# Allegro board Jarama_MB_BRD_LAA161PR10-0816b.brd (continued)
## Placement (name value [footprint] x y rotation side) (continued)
PQ601  -  [MDV1528URH_PDFN33-8-5]  84.55 31.15 0 top
PQ602  -  [MDV1524URH_PDFN33-8-5]  90.12 34.1 180 top
PR102  -  [R_0402]  24.2 59.85 90 top
PR103  -  [R_0402]  24.2 62.54 270 top
PR104  -  [R_0402]  24.19 64.45 270 top
PR105  -  [R_0402]  26.85 65.95 90 top
PR106  -  [R_0402]  26.85 67.72 90 top
PR108  -  [R_0402]  199.46 22.92 270 top
PR109  -  [R_0402]  65.08 12.25 90 top
PR110  -  [R_0402]  194.49 23.41 0 top
PR111  -  [R_0402]  64.19 12.25 90 top
PR112  -  [R_0402]  63.21 12.24 180 top
PR113  -  [R_0402]  61.44 12.24 180 top
PR115  -  [R0402_0OHM]  58.87 7.63 180 top
PR116  -  [R_0402]  99.62 2.73 270 bottom
PR118  -  [R_0402]  101.39 1.81 90 bottom
PR119  -  [R_0402]  103.19 1.81 90 bottom
PR120  -  [R_0402]  107.87 5.19 270 bottom
PR121  -  [R_0402]  107.87 3.31 270 bottom
PR122  -  [R_1206]  106.46 7.16 270 bottom
PR123  -  [R_0402]  197.95 20.07 0 top
PR124  -  [R_0402]  200.67 19.19 180 top
PR125  -  [R_0402]  198.86 19.19 180 top
PR126  -  [R_0402]  202.47 19.19 180 top
PR201  -  [R_1206_4P-D]  70.71 13.95 0 top
PR202  -  [R_0603]  28.95 56.37 180 top
PR203  -  [R_0402]  28.84 57.51 180 bottom
PR206  -  [R_0402]  27.79 55.23 0 top
PR208  -  [R_0402]  101.76 3.46 180 top
PR209  -  [R_1206]  105.39 9.05 180 bottom
PR210  -  [R_1206]  105.4 11.03 180 bottom
PR211  -  [R_0603]  97.72 10.08 90 bottom
PR213  -  [R_0402]  101.4 4.35 90 top
PR216  -  [R_1206_4P-D]  91.69 18.61 270 bottom
PR220  -  [R_1206]  85.46 13.7 0 bottom
PR223  -  [R_0402]  103.19 3.56 180 bottom
PR224  -  [R_0402]  96.7 2.73 270 bottom
PR225  -  [R_0402]  91.64 1.68 90 bottom
PR226  -  [R_0402]  102.28 4.45 0 bottom
PR230  -  [R_0402]  95.14 4.43 180 top
PR238  -  [R0402_0OHM]  102.33 1.81 90 bottom
PR239  -  [R0402_0OHM]  98.62 2.73 270 bottom
PR240  -  [R0402_0OHM]  97.61 2.73 270 bottom
PR311  -  [R_0402]  192.46 30.59 90 top
PR312  -  [R_1206]  191.06 45.83 0 bottom
PR313  -  [R_1206]  189.29 46.08 180 bottom
PR316  -  [R_0402]  189.77 31.5 270 top
PR318  -  [R_0402]  189.55 32.8 90 bottom
PR335  -  [R0402_0OHM]  190.7 30.59 90 top
PR344  -  [R0402_0OHM]  195.33 33.64 180 top
PR345  -  [R0402_0OHM]  187.64 33.28 180 top
PR348  -  [R_0402]  192.86 35.24 270 bottom
PR351  -  [R_0402]  188.21 34.91 0 bottom
PR352  -  [R_0402]  191.33 33.71 270 bottom
PR353  -  [R_0402]  191.57 30.59 90 top
PR354  -  [R_0402]  190.44 32.8 90 bottom
PR355  -  [R_0603]  195.83 36.05 180 top
PR356  -  [R_0603]  186.81 35.86 180 top
PR404  -  [R0402_0OHM]  91.5 50.22 270 top
PR405  -  [R0402_0OHM]  227.87 40.76 180 top
PR422  -  [R_0402]  84.45 49.13 0 top
PR425  -  [R_0402]  85.36 51.8 180 top
PR427  -  [R_0402]  84.45 50.02 0 top
PR428  -  [R0402_0OHM]  84.45 52.69 0 top
PR429  -  [R_1206]  89.73 54.4 270 bottom
PR432  -  [R_1206]  222.7 38.65 270 bottom
PR433  -  [R_0402]  224.59 35.53 90 top
PR434  -  [R0402_0OHM]  221.18 38.41 270 top
PR437  -  [R_0402]  225.49 35.53 90 top
PR438  -  [R_0402]  222.64 36.43 180 top
PR505  -  [R0402_0OHM]  198.38 56.88 180 top
PR506  -  [R_0603]  196.91 64.31 90 top
PR507  -  [R_1206]  197.39 65.83 270 bottom
PR508  -  [R0402_0OHM]  198.39 57.77 180 top
PR601  -  [R_0603]  91.43 33.26 0 bottom
PR604  -  [R_0402]  93.91 29.5 90 bottom
PR605  -  [R_1206]  90.1 34.59 90 bottom
PR606  -  [R_0603]  97.42 31.1 0 bottom
PR608  -  [R_0402]  101.68 37.07 180 bottom
PR610  -  [R_0402]  100.77 34.91 0 bottom
PR611  -  [R_0402]  101.68 31.35 180 bottom
PR613  -  [R0402_0OHM]  101.68 32.24 180 bottom
PR615  -  [R0402_0OHM]  101.68 34.02 180 bottom
PR701  -  [R_0402]  105.81 60.69 180 bottom
PR702  -  [R_0402]  97.4 44.23 90 top
PR703  -  [R_0402]  104.7 59.5 270 top
PR704  -  [R_0402]  105.81 58.91 180 bottom
PR706  -  [R_0402]  102.48 53.88 90 top
PR707  -  [R_0402]  99.23 45.19 0 top
PR708  -  [R_0402]  99.23 44.18 0 top
PR709  -  [R_0402]  103.38 59.16 180 bottom
PR710  -  [R_0402]  105.64 58.53 0 top
PR711  -  [R_0402]  103.38 58.28 180 bottom
PR712  -  [R_0402]  104.26 54.8 270 top
PR713  -  [R_0402]  103.37 54.8 270 top
PR714  -  [R_0402]  103.4 60.94 180 bottom
PR715  -  [R_0603]  92.08 51.8 0 top
PR717  -  [R_0402]  104.7 61.53 270 top
PR718  -  [R0402_0OHM]  100.73 55.01 180 bottom
PR719  -  [R_1206]  101.48 48.12 180 bottom
PR720  -  [R_0402]  100.73 54.02 180 bottom
PR721  -  [R_0402]  101.02 56.42 90 bottom
PR723  -  [R_0402]  101.15 54.8 270 top
PR725  -  [R_0603]  100.01 55.04 270 top
PR726  -  [R_0402]  97.28 60.26 270 top
PR727  -  [R_0402]  97.28 62.04 270 top
PR731  -  [R_0603]  95.76 58.15 0 top
PR735  -  [R_0402]  95.43 54.9 90 top
PR736  -  [R_0402]  96.64 55.86 0 top
PR737  -  [R_0402]  96.37 54.85 0 top
PR744  -  [R_0402]  95.4 61.54 180 top
PR745  -  [R_0402]  105.15 53.88 90 top
PU201  -  [BQ24715RGRR_QFN20_3P5X3P5]  100.46 7.21 270 bottom
PU301  -  [TPS51285BRUKR_QFN20_3X3]  189.76 33.29 0 top
PU405  -  [TLV62150RGTR_QFN16_3X3]  89.08 51.51 180 top
PU406  -  [TLV62150RGTR_QFN16_3X3]  222.61 40.1 270 top
PU501  -  [TPS51362RVER_QFN28_4P5X3P5]  198.02 62.85 180 top
PU601  -  [G5616ARZ1U_TQFN20_3X3]  96.03 35.82 0 bottom
PU701  -  [TPS51622RSM_QFN32_4X4]  99.63 56.87 0 top
PU702  -  [CSD97374CQ4M_SON8_3P5X4P5]  98.44 53.14 270 bottom
Q4  -  [SSM3K7002FU_SC70-3]  197.69 49.33 180 bottom
Q5  -  [SSM3K7002FU_SC70-3]  177.82 68.31 90 top
Q6  -  [SSM3K7002FU_SC70-3]  16.07 18.55 180 bottom
Q34  -  [SSM3K7002FU_SC70-3]  257.74 53.01 0 top
Q39  -  [SSM3K7002FU_SC70-3]  177.03 61.69 0 bottom
Q70  -  [SI3457BDV-T1-E3_TSOP6]  91.39 65.68 90 top
Q71  -  [SSM3K7002FU_SC70-3]  93.68 67.52 180 top
Q107  -  [SSM3K7002FU_SC70-3]  23.95 21 180 bottom
Q134  -  [SSM3K7002FU_SC70-3]  38.97 21.37 90 top
Q135  -  [SSM3K7002FU_SC70-3]  191.24 62.66 0 top
Q136  -  [SSM3K7002FU_SC70-3]  191.17 67.52 270 top
Q305  -  [SSM3K7002FU_SC70-3]  90.42 60.84 270 top
Q311  -  [SSM3K7002FU_SC70-3]  155.58 11.59 270 bottom
Q326  -  [SSM3K7002FU_SC70-3]  141.66 9.38 180 bottom
Q329  -  [AO3419L_SOT23-3]  141.67 5.19 180 bottom
Q330  -  [AO3419L_SOT23-3]  189.03 68.97 0 bottom
Q344  -  [SSM3K7002FU_SC70-3]  226.4 46.71 0 top
Q346  -  [SSM3K7002FU_SC70-3]  228.79 46.69 0 top
Q347  -  [MMBT3904_SOT23-3]  223.09 46.65 0 top
Q348  -  [SSM3K7002FU_SC70-3]  174.17 52.49 180 top
Q350  -  [SSM3K7002FU_SC70-3]  169.34 52.54 90 bottom
Q351  -  [SSM3K7002FU_SC70-3]  163.33 31.61 90 bottom
Q352  -  [DMN66D0LDW-7_SOT363-6]  202.81 51.53 90 top
Q359  -  [DMN66D0LDW-7_SOT363-6]  251.2 47.68 270 top
Q360  -  [SIS412DN-T1-GE3_POWERPAK8-5]  181.1 60.66 270 top
Q361  -  [SI1553CDL-T1-GE3_SC70-6]  182.54 59.17 0 bottom
Q362  -  [SSM3K7002FU_SC70-3]  183.72 60.94 270 bottom
Q363  -  [SSM3K7002FU_SC70-3]  177.03 59.16 0 top
Q364  -  [SSM3K7002FU_SC70-3]  197.85 8.62 90 bottom
Q365  -  [SSM3K7002FU_SC70-3]  164.21 10.94 270 bottom
Q366  -  [DMN66D0LDW-7_SOT363-6]  271.36 42.61 180 top
Q367  -  [DMN66D0LDW-7_SOT363-6]  270.06 43.76 0 top
QA1  -  [DMN66D0LDW-7_SOT363-6]  15.42 17.32 0 bottom
QA3  -  [DMN66D0LDW-7_SOT363-6]  20.46 13.76 180 top
QA6  -  [DMN66D0LDW-7_SOT363-6]  18.46 3.86 0 top
QC5  -  [SSM3K7002FU_SC70-3]  155.89 68.62 180 top
QH3  -  [DMN66D0LDW-7_SOT363-6]  178.32 55.27 270 top
QH4  -  [DMN66D0LDW-7_SOT363-6]  213.94 68.24 180 top
R1  -  [R_0402]  270.58 38.79 90 top
R4  -  [R_0402]  269.07 44.79 90 top
R7  -  [R_0402]  33.13 20.05 0 top
R11  -  [R_0402]  279.38 38.12 90 top
R23  -  [R_0402]  23.37 3.39 270 top
R24  -  [R_0402]  29.22 3.39 270 top
R25  -  [R_0402]  18.13 15.45 0 bottom
R26  -  [R_0402]  24.26 2.47 90 top
R27  -  [R_0402]  28.33 2.47 90 top
R31  -  [R_0402]  35.59 23.07 0 top
R34  -  [R_0402]  30.41 7.45 0 top
R36  -  [R_0402]  271.6 39.71 270 top
R162  -  [R_0402]  188.88 66.91 180 top
R163  -  [R_0402]  189.46 68.13 90 top
R216  -  [R0603_0OHM]  213.8 48.94 90 top
R219  -  [R_0402]  204.53 47.68 270 top
R221  -  [R_0402]  213.1 48.19 270 bottom
R225  -  [R_0402]  206.31 46.79 90 top
R229  -  [R_0402]  204.74 49.64 180 bottom
R230  -  [R_0402]  204.74 50.53 180 bottom
R232  -  [R_0402]  215.27 46.22 180 bottom
R233  -  [R_0402]  204.2 50.27 0 top
R240  -  [R_0402]  203 59.09 90 top
R253  -  [R0402_0OHM]  212.16 59.11 270 bottom
R265  -  [R0402_0OHM]  105.02 39.16 90 bottom
R290  -  [R_0402]  172.92 67.04 0 top
R296  -  [R_0402]  257.74 50.96 90 top
R297  -  [R_0402]  195.83 49 0 bottom
R298  -  [R_0402]  179.95 68.11 90 top
R300  -  [R_0402]  177.16 63.33 180 bottom
R341  -  [R_0402]  204.78 40.83 270 top
R342  -  [R_0402]  196.35 30.08 180 top
R501  -  [R_0402]  197.61 59.67 0 bottom
R503  -  [R_0402]  197.61 58.78 0 bottom
R531  -  [R_0603]  87.23 67.99 270 top
R535  -  [R_0402]  90.15 67.27 0 bottom
R536  -  [R_0402]  91.94 67.27 0 bottom
R537  -  [R_0402]  238.96 57.39 0 top
R540  -  [R_0402]  174.76 69.02 270 top
R541  -  [R_0805]  91.6 64.31 270 top
R545  -  [R_0402]  171.82 69.58 0 bottom
R604  -  [R_0402]  213.99 47.28 90 bottom
R607  -  [R_0402]  211.27 59.11 270 bottom
R608  -  [R_0402]  106.67 37.03 270 bottom
R741  -  [R_0402]  221.11 59.34 90 top
R742  -  [R_0402]  220.1 59.34 90 top
R743  -  [R_0402]  232.42 38.73 270 top
R744  -  [R_0402]  231.4 38.73 270 top
R746  -  [R_0402]  201.73 60.77 270 top
R819  -  [R0402_0OHM]  244.05 60.9 270 top
R854  -  [R_0402]  240.04 59.29 180 top
R855  -  [R_0402]  240.04 60.18 180 top
R884  -  [R_0402]  47.53 3.81 270 top
R886  -  [R_0402]  51 2.9 270 bottom
R921  -  [R0402_0OHM]  214.23 51.42 0 top
R922  -  [R_0402]  204.23 54.59 180 bottom
R923  -  [R_0402]  186.35 69.77 270 bottom
R924  -  [R0402_0OHM]  187.53 67.8 0 top
R930  -  [R_0402]  209.86 59.11 270 top
R931  -  [R_0402]  208.03 58.15 180 top
R933  -  [R_0402]  214.55 40.39 0 bottom
R934  -  [R0402_0OHM]  211.64 58.2 90 top
R935  -  [R_0402]  207.97 58.2 90 bottom
R936  -  [R_0402]  215.46 41.28 180 bottom
R937  -  [R_0402]  180.94 26.2 0 top
R938  -  [R_0402]  182.8 26.31 90 top
R939  -  [R_0402]  202.2 56.37 180 bottom
R940  -  [R_0402]  152.27 31.22 0 bottom
R942  -  [R_0402]  223.65 50.59 180 top
R943  -  [R_0402]  140.02 9.05 90 bottom
R944  -  [R_0402]  157.8 12.17 270 bottom
R945  -  [R_0402]  158.69 11.26 90 bottom
R946  -  [R_0402]  153.18 32.11 180 bottom
R947  -  [R_0402]  133.89 46.57 270 top
R948  -  [R_0402]  134.77 45.65 90 top
R949  -  [R_0402]  83.61 67.52 0 top
R950  -  [R_0402]  156.79 11.26 90 bottom
R951  -  [R_0402]  83.61 66.61 270 top
R953  -  [R_0402]  37.57 15.4 0 bottom
R955  -  [R_0402]  40.66 8.34 270 bottom
R957  -  [R_0402]  106.44 64.24 180 bottom
R973  -  [R_0402]  186.12 12.51 270 bottom
R974  -  [R0402_0OHM]  185.24 11.59 90 bottom
R975  -  [R_0402]  209.35 39.28 90 top
R976  -  [R_0402]  199.79 50.12 270 bottom
R977  -  [R_0402]  200.65 50.35 0 bottom
R978  -  [R_0402]  200.65 52.13 0 bottom
R979  -  [R_0402]  200.65 51.24 0 bottom
R982  -  [R0402_0OHM]  208.97 58.2 90 top
R983  -  [R0402_0OHM]  215.83 67.47 90 top
R984  -  [R0402_0OHM]  211.78 63.79 90 top
R985  -  [R_0402]  215.86 66.61 180 top
R986  -  [R_0402]  212.67 63.79 90 top
R987  -  [R0402_0OHM]  208.91 52.7 270 top
R988  -  [R0402_0OHM]  189.53 65.97 0 top
R989  -  [R_0402]  143.33 9.94 90 bottom
R990  -  [R0402_0OHM]  195.22 67.31 90 top
R1003  -  [R_0402]  240.04 61.96 180 top
R1004  -  [R_0402]  215.21 59.24 90 top
R1005  -  [R_0402]  216.19 59.25 90 top
R1006  -  [R_0402]  132.64 68.04 90 top
R1007  -  [R_0402]  133.66 68.04 90 top
R1008  -  [R_0402]  134.68 68.04 90 top
R1009  -  [R_0402]  135.69 68.04 90 top
R1010  -  [R_0402]  137.41 68.05 90 top
R1011  -  [R_0402]  138.42 68.05 90 top
R1012  -  [R_0402]  131.63 68.04 90 top
R1013  -  [R_0402]  130.61 68.04 90 top
R1014  -  [R_0402]  128.58 68.04 90 top
R1015  -  [R_0402]  129.66 68.04 90 top
R1016  -  [R0402_0OHM]  137.48 71.79 0 top
R1017  -  [R0402_0OHM]  137.48 70.93 0 top
R1026  -  [R_0402]  188.28 50.58 180 top
R1033  -  [R_0402]  138.35 66.49 0 top
R1034  -  [R_0402]  136.57 66.49 0 top
R1035  -  [R_0402]  238.31 42.45 90 top
R1036  -  [R_0402]  235.64 42.45 90 top
R1090  -  [R_0402]  240.06 62.82 180 top
R1092  -  [R_0402]  243.19 59.57 180 top
R1099  -  [R_0402]  241.08 55.96 0 top
R1100  -  [R_0402]  184.35 12.51 270 bottom
R1103  -  [R_0402]  49.85 4.05 0 bottom
R1116  -  [R_0402]  252.23 67.8 180 top
R1117  -  [R_0402]  264.47 53.88 90 top
R1118  -  [R_0402]  265.36 53.88 90 top
R1119  -  [R_0402]  27.5 44.06 270 top
R1120  -  [R_0402]  28.39 44.06 270 top
R1125  -  [R0603_0OHM]  36 12.45 270 bottom
R1128  -  [R0603_0OHM]  238.25 46.34 0 top
R1129  -  [R_0603]  200.84 55.29 270 top
R1131  -  [R0402_0OHM]  218.07 54.59 180 top
R1132  -  [R_0402]  117.07 51.04 0 top
R1133  -  [R0402_0OHM]  210.75 58.2 90 top
R1135  -  [R0402_0OHM]  251.31 68.69 0 top
R1136  -  [R_0402]  251.31 69.55 0 top
R1137  -  [R_0402]  227.34 49.96 180 top
R1140  -  [R_0402]  33.96 17.75 90 bottom
R1141  -  [R_0402]  240.06 63.71 180 top
R1142  -  [R_0402]  187.01 11.59 90 bottom
R1143  -  [R_0402]  251.31 66.91 0 top
R1152  -  [R_0402]  126.52 65.08 90 top
R1153  -  [R_0402]  127.77 65.08 90 top
R1156  -  [R_0402]  203.32 56.24 0 bottom
R1157  -  [R_0402]  141.03 66.53 0 top
R1158  -  [R0402_0OHM]  252.02 63.66 90 top
R1161  -  [R_0402]  95.38 66.32 0 top
R1162  -  [R_0402]  188.28 49.69 180 top
R1164  -  [R_0402]  261.75 49.64 180 top
R1165  -  [R_0402]  267.9 46.98 270 top
R1166  -  [R0402_0OHM]  265.88 46.98 270 top
R1167  -  [R0402_0OHM]  27.63 50.26 90 top
R1168  -  [R_0402]  25.85 50.26 90 top
R1169  -  [R_0402]  180.66 60.16 90 bottom
R1170  -  [R_0402]  261.75 48.75 180 top
R1174  -  [R_0402]  232.92 46.46 180 top
R1179  -  [R_0402]  117.29 58.71 180 bottom
R1180  -  [R_0402]  111.31 56.62 0 top
R1182  -  [R_0402]  33.07 17.75 90 bottom
R1185  -  [R_0402]  181.88 56.35 270 top
R1186  -  [R_0402]  37.98 4.49 180 top
R1187  -  [R_0402]  36.12 3.42 270 top
R1188  -  [R0402_0OHM]  236.1 69.71 180 top
R1190  -  [R_0402]  184.8 64.75 180 bottom
R1197  -  [R_0402]  229.99 49.94 90 top
R1198  -  [R_0402]  119.37 49.64 0 bottom
R1200  -  [R_0402]  172.52 51.24 270 top
R1202  -  [R_0402]  216.87 46.08 180 top
R1203  -  [R_0402]  221.44 50.61 90 top
R1204  -  [R0402_0OHM]  230.13 69.71 180 top
R1205  -  [R_0402]  172.48 53.32 0 bottom
R1208  -  [R_0402]  264.66 27.16 0 bottom
R1209  -  [R0402_0OHM]  225.48 51.49 270 top
R1210  -  [R_0402]  224.59 51.49 270 top
R1211  -  [R_0402]  115.51 58.73 270 bottom
R1212  -  [R_0402]  225.48 45.68 180 top
R1213  -  [R_0402]  267.02 46.98 270 top
R1214  -  [R_0402]  26.74 50.26 90 top
R1215  -  [R_0402]  217.79 52.43 0 top
R1216  -  [R_0402]  264.72 46.07 90 top
R1217  -  [R_0402]  28.89 51.11 270 top
R1218  -  [R0402_0OHM]  126.52 66.91 270 top
R1219  -  [R0402_0OHM]  127.77 66.91 270 top
R1220  -  [R_0402]  249.21 58.16 0 top
R1221  -  [R0402_0OHM]  247.84 57.25 90 top
R1222  -  [R0402_0OHM]  246.95 57.25 90 top
R1223  -  [R_0402]  246.06 58.17 270 top
R1224  -  [R_0402]  164.79 66.07 90 top
R1225  -  [R_0402]  165.68 66.07 90 top
R1226  -  [R0603_0OHM]  236.91 50.21 90 top
R1227  -  [R0402_0OHM]  141.08 68.82 270 top
R1228  -  [R_0402]  183.46 11.59 90 bottom
R1229  -  [R_0402]  251.31 66.02 0 top
R1230  -  [R_0402]  237.18 57.39 0 top
R1231  -  [R0402_0OHM]  216.77 51.9 270 top
R1232  -  [R0402_0OHM]  216.77 49.82 270 top
R1233  -  [R_0402]  215.84 49.84 270 top
R1234  -  [R_0402]  241.89 58.71 0 top
R1235  -  [R_0402]  241.66 57.83 0 top
R1236  -  [R_0402]  241.66 56.92 0 top
R1237  -  [R_0402]  240.71 58.16 270 top
R1238  -  [R0402_0OHM]  212.99 45.93 180 top
R1239  -  [R_0402]  212.99 45.04 180 top
R1240  -  [R_1206]  176.64 63.78 90 top
R1241  -  [R_0402]  244.56 42.05 180 top
R1242  -  [R0603_0OHM]  191.52 11.54 180 bottom
R1243  -  [R_0402]  243.39 43.86 270 top
R1249  -  [R_0402]  215.23 55.46 180 bottom
R1250  -  [R_0402]  238.99 51.93 0 top
R1251  -  [R_0402]  245.17 58.17 270 top
R1252  -  [R0402_0OHM]  256.09 52.36 90 top
R1253  -  [R_0402]  256.09 55.18 270 top
R1255  -  [R_0402]  228.21 50.91 0 top
R1256  -  [R_0402]  228.21 51.8 0 top
R1257  -  [R0402_0OHM]  170.88 12.25 270 bottom
R1258  -  [R0402_0OHM]  170 12.25 270 bottom
R1260  -  [R0603_0OHM]  190.32 51.02 270 bottom
R1261  -  [R_0402]  40.24 17.63 270 bottom
R1262  -  [R_0402]  39.35 17.62 270 bottom
R1263  -  [R_0402]  40.66 9.25 0 bottom
R1264  -  [R_0402]  36.88 17.52 270 top
R1265  -  [R_0402]  41.55 11.06 270 bottom
R1266  -  [R_0402]  37.77 17.52 270 top
R1289  -  [R_0402]  182.26 36.5 270 top
R1290  -  [R_0402]  180.41 30.92 270 top
R1291  -  [R_0402]  181.37 36.5 270 top
R1292  -  [R_0402]  185.98 30.29 270 top
R1294  -  [R0402_0OHM]  181.32 30.92 270 top
R1295  -  [R_0402]  180.41 31.78 90 top
R1296  -  [R_0402]  180.4 36.2 270 top
R1297  -  [R0402_0OHM]  180.4 33.55 90 top
R1300  -  [R_0402]  195.83 8.09 0 bottom
R1301  -  [R_0402]  166.24 10.74 90 bottom
R1305  -  [R_0603]  49.02 9.13 0 top
R1306  -  [R_0603]  48.56 6.63 90 top
R1309  -  [R0402_0OHM]  117.38 51.44 180 bottom
R1310  -  [R_0402]  207.07 41.82 90 top
R1311  -  [R_0402]  116.47 52.33 0 bottom
R1312  -  [R_0402]  174.48 45.58 0 top
R1313  -  [R_0402]  221.75 54.14 180 top
R1314  -  [R0402_0OHM]  221.51 53.25 180 top
R1318  -  [R0603_0OHM]  32.19 13.89 270 bottom
R1319  -  [R0603_0OHM]  244.81 51.34 0 top
R1320  -  [R0603_0OHM]  167.76 68.88 180 top
R1321  -  [R_0603]  192.33 49.1 0 bottom
R1322  -  [R0805_0OHM]  194.17 51 90 top
R1324  -  [R_0402]  89.39 64.45 270 top
R1325  -  [R_0402]  88.5 64.45 270 top
R1326  -  [R_0603]  167.82 67.29 270 top
R1327  -  [R_0402]  217.15 55.48 0 top
R1328  -  [R_0402]  217.15 56.37 0 top
R1330  -  [R0603_0OHM]  243.69 54.06 90 top
R1331  -  [R0603_0OHM]  55.21 12.38 0 top
R1338  -  [R_0402]  216.87 46.97 180 top
R1339  -  [R_0402]  223.65 51.54 180 top
R1340  -  [R_0402]  245.5 42.03 0 top
R1341  -  [R_0402]  166.87 31.35 0 bottom
R1342  -  [R_0402]  210.75 64.63 270 top
R1343  -  [R_0402]  248.34 43.37 270 top
R1346  -  [R_0402]  249.28 47.03 0 top
R1347  -  [R_0402]  249.28 47.92 0 top
R1348  -  [R_0402]  239.91 50.9 180 top
R1349  -  [R_0402]  239.91 50.02 180 top
R1350  -  [R_0402]  252.61 48.81 180 top
R1351  -  [R_0402]  251.18 45.25 0 top
R1353  -  [R0402_0OHM]  121.72 54.54 270 top
R1355  -  [R_1206]  184.54 63.23 180 bottom
R1360  -  [R_0402]  218.93 62.59 0 top
R1361  -  [R_0402]  217.15 60.82 0 top
R1362  -  [R_0402]  217.15 59.93 0 top
R1363  -  [R_0402]  217.15 59.04 0 top
R1364  -  [R_0402]  217.15 58.15 0 top
R1365  -  [R_0402]  217.15 57.26 0 top
R1366  -  [R_0402]  203.84 27.57 0 top
R1367  -  [R_0402]  250.93 58.16 0 top
R1368  -  [R_0402]  224.77 56.37 0 top
R1369  -  [R_0402]  224.77 57.26 0 top
R1370  -  [R_0402]  224.77 54.59 0 top
R1371  -  [R_0402]  224.77 55.48 0 top
R1372  -  [R0402_0OHM]  32.3 11.82 90 top
R1373  -  [R_0402]  35.23 4.54 90 top
R1374  -  [R_0402]  36.12 4.54 90 top
R1376  -  [R_0402]  141.97 68.82 270 top
R1379  -  [R_0603]  195.76 52.37 90 top
R1380  -  [R0603_0OHM]  264.85 11.48 90 top
R1381  -  [R_0402]  184.68 57.03 180 top
R1382  -  [R_0402]  181.59 59.29 180 bottom
R1383  -  [R_0402]  181.5 58.05 180 bottom
R1384  -  [R_0402]  175.06 55.91 90 top
R1385  -  [R_0402]  175.2 58.61 270 top
R1386  -  [R_0402]  215.16 49.39 270 bottom
R1387  -  [R0402_0OHM]  196.73 9.05 180 bottom
R1388  -  [R0402_0OHM]  165.35 10.74 90 bottom
R1389  -  [R0603_0OHM]  203.89 8.68 90 top
R1390  -  [R_0402]  232.92 50.78 180 top
RA1  -  [R_0402]  45.21 12.73 180 top
RA2  -  [R0603_0OHM]  22.22 18.97 180 top
RA3  -  [R0402_0OHM]  15.17 12.38 270 bottom
RA4  -  [R0402_0OHM]  15.04 16.57 270 top
RA5  -  [R_0402]  201.81 65.9 180 top
RA6  -  [R_0402]  201.86 67.72 90 top
RA7  -  [R_0402]  166.57 66.99 270 top
RA8  -  [R_0402]  163.76 66.99 270 top
RA9  -  [R0402_0OHM]  201.81 66.78 180 top
RA10  -  [R0402_0OHM]  200.97 67.72 90 top
RA11  -  [R0402_0OHM]  44.3 15.81 0 top
RA12  -  [R0402_0OHM]  44.3 14.93 0 top
RA13  -  [R0402_0OHM]  44.3 14.04 0 top
RA14  -  [R_0402]  13.54 9.25 90 top
RA15  -  [R_0402]  15.2 13.25 180 bottom
RA16  -  [R_0402]  16.64 13.51 90 bottom
RA17  -  [R_0402]  14.37 18.33 180 top
RA18  -  [R_0402]  18.12 21.67 0 bottom
RA20  -  [R_0402]  20.37 7.49 90 top
RA21  -  [R_0402]  18.09 17.12 90 top
RA22  -  [R_0402]  17.07 17.12 90 top
RA23  -  [R_0402]  19.11 21.64 270 top
RA24  -  [R_0402]  21.22 22.84 180 top
RA25  -  [R_0402]  21.22 21.83 180 top
RA26  -  [R0402_0OHM]  19.11 10.88 270 top
RA27  -  [R_0402]  15.22 18.4 0 top
RA28  -  [R_0402]  16.64 12.45 0 bottom
RA29  -  [R_0402]  32.33 21.83 180 top
RA30  -  [R_0402]  34.74 23.05 180 top
RA31  -  [R_0402]  34.04 19.16 180 top
RA32  -  [R0603_0OHM]  31.49 29.19 0 top
RA33  -  [R_0402]  34.04 18.27 180 top
RA35  -  [R_0402]  17.8 6.71 180 top
RA36  -  [R_0402]  32.52 25.64 180 bottom
RA37  -  [R_0402]  18.22 14.77 90 top
RA38  -  [R_0402]  20 9.97 90 top
RA39  -  [R_0402]  19.11 14.77 90 top
RA41  -  [R_0402]  22.29 21.9 270 bottom
RA42  -  [R_0402]  23.62 24.11 0 bottom
RA43  -  [R_0402]  13.53 17.2 270 bottom
RA44  -  [R_0402]  19.11 18.84 90 top
RA45  -  [R_0402]  14.45 19.11 180 bottom
RA46  -  [R_0603]  30.68 6.52 270 bottom
RA47  -  [R_0603]  20.96 2.68 0 top
RA48  -  [R_0402]  14.37 20.11 180 top
RA49  -  [R_0402]  15.18 14.21 180 bottom
RA50  -  [R_0402]  14.37 19.22 180 top
RA51  -  [R_0402]  14.41 16 270 bottom
RA52  -  [R_0402]  32.26 20.94 180 top
RA53  -  [R_0402]  32.52 26.53 180 bottom
RA54  -  [R_0402]  32.33 23.6 180 top
RA55  -  [R_0402]  22.13 7.51 180 top
RA56  -  [R_0402]  30.79 13.24 90 top
RA57  -  [R0402_0OHM]  18.34 20.79 270 bottom
RA58  -  [R_0402]  47.96 13.8 90 top
RA59  -  [R_0402]  48.89 13.8 90 top
RA60  -  [R_0402]  46.06 12.73 0 top
RA61  -  [R_0402]  47.05 13.8 90 top
RA62  -  [R_0402]  46.13 13.8 90 top
RA68  -  [R_0603]  31.56 5.18 180 top
RA69  -  [R_0603]  22.36 3.89 180 top
RA75  -  [R_0402]  13.53 20.14 0 bottom
RC36  -  [R_0402]  151.24 57.51 0 top
RC41  -  [R_0402]  116.38 56.93 0 bottom
RC43  -  [R_0402]  116.38 57.82 0 bottom
RC44  -  [R_0402]  117 57.03 0 top
RC45  -  [R_0402]  120.36 58.81 180 bottom
RC46  -  [R_0402]  120.36 60.59 180 bottom
RC48  -  [R_0402]  120.36 59.7 180 bottom
RC49  -  [R0402_0OHM]  117.75 60.69 180 bottom
RC52  -  [R_0402]  122.87 56.96 270 top
RC54  -  [R_0402]  121.76 56.95 270 top
RC55  -  [R_0402]  130.1 47.1 270 top
RC58  -  [R_0402]  131.43 45.45 0 top
RC60  -  [R_0402]  131.43 46.97 0 top
RC75  -  [R_0402]  153.05 33.31 90 bottom
RC81  -  [R_0402]  120.28 50.53 180 bottom
RC92  -  [R0402_0OHM]  117.67 54.29 270 bottom
RC93  -  [R_0402]  120.21 53.65 90 bottom
RC94  -  [R_0402]  119.32 54.57 270 bottom
RC95  -  [R_0402]  120.64 55.48 0 bottom
RC96  -  [R0402_0OHM]  117.09 55.86 0 bottom
RC97  -  [R_0402]  119.45 64.14 0 bottom
RC98  -  [R0402_0OHM]  119.45 63.23 0 bottom
RC99  -  [R0402_0OHM]  120.36 62.37 180 bottom
RC100  -  [R_0402]  120.36 61.48 180 bottom
RC138  -  [R_0402]  153.36 68.89 270 top
RC146  -  [R_0402]  139.3 67.9 90 top
RC147  -  [R0402_0OHM]  160.34 66.99 270 bottom
RC148  -  [R0402_0OHM]  154.23 67.98 90 top
RC149  -  [R_0402]  116.83 59.8 0 bottom
RC150  -  [R0402_0OHM]  116.83 61.58 0 bottom
RC151  -  [R0402_0OHM]  116.96 57.89 0 top
RC152  -  [R0402_0OHM]  114.62 57.82 90 bottom
RC153  -  [R_0402]  121.68 51.42 180 bottom
RC154  -  [R_0402]  152.9 36 270 bottom
RC155  -  [R_0402]  155.01 66.91 0 bottom
RC156  -  [R_0402]  152.01 36 270 bottom
RC158  -  [R_0402]  140.19 68.82 270 top
RC159  -  [R_0402]  124.71 32.62 0 bottom
RC160  -  [R_0402]  154.18 66.53 180 top
RC161  -  [R_0402]  125.62 31.73 180 bottom
RC162  -  [R0402_0OHM]  153.79 36 270 bottom
RD1  -  [R_0402]  99.76 19.6 180 top
RD2  -  [R_0402]  109.85 21.81 90 top
RD5  -  [R_0402]  128.82 18.33 0 top
RD6  -  [R_0402]  134.61 20.44 270 top
RD7  -  [R_0402]  146.37 18.33 180 top
RD8  -  [R_0402]  157.09 20.44 270 top
RD11  -  [R_0402]  175.94 18.33 0 top
RD12  -  [R_0402]  180.9 24.42 90 top
RD13  -  [R_0402]  119.69 48.01 270 top
RD14  -  [R_0402]  120.61 45.35 180 top
RD15  -  [R_0402]  120.58 47.1 90 top
RD16  -  [R_0402]  121.47 47.1 90 top
RD17  -  [R_0402]  112.5 45.58 0 top
RD18  -  [R_0402]  117.91 47.33 270 top
RD19  -  [R_0402]  115.2 45.58 180 top
RD20  -  [R_0402]  117.02 45.5 90 top
RD21  -  [R_0402]  113.42 46.46 180 top
RD22  -  [R_0402]  117 47.51 90 top
RD23  -  [R_0402]  115.2 46.46 180 top
RD24  -  [R_0402]  118.8 46.41 90 top
RD25  -  [R_0402]  121.45 16.4 180 top
RD26  -  [R_0402]  167.05 18.45 0 top
RD27  -  [R_0402]  119.93 18.71 0 top
RD28  -  [R_0402]  169.75 18.45 180 top
RD29  -  [R_0402]  123.69 14.7 0 top
RD30  -  [R_0402]  165.42 14.9 180 top
RD31  -  [R_0402]  124.45 22.32 90 top
RD32  -  [R_0402]  170.68 20.54 90 top
RD33  -  [R_0402]  121.73 15.15 180 top
RD34  -  [R_0402]  166.19 12.73 90 top
RD35  -  [R_0402]  117.97 13.55 90 top
RD36  -  [R_0402]  168.33 14.82 90 top
RD37  -  [R_0402]  123.65 15.64 0 top
RD38  -  [R_0402]  170.88 16.17 180 top
RD39  -  [R_0402]  122.13 13.12 0 top
RD40  -  [R_0402]  163.87 12.87 180 top
RD41  -  [R_0402]  125.77 14.64 0 top
RD42  -  [R_0402]  170.31 12.66 0 top
RD43  -  [R_0402]  123.93 13.06 0 top
RD44  -  [R_0402]  172.08 13.71 270 top
RD45  -  [R_0402]  118.86 13.68 90 top
RD46  -  [R_0402]  173.85 12.79 90 top
RD47  -  [R_0402]  116.85 12.68 180 top
RD48  -  [R_0402]  172.96 12.79 90 top
RD49  -  [R_0402]  120.58 12.61 90 top
RD50  -  [R_0402]  166.26 14.9 0 top
RD51  -  [R_0402]  126.73 12.68 0 top
RD52  -  [R_0402]  168.01 12.78 90 top
RD53  -  [R_0402]  125.79 12.61 90 top
RD54  -  [R_0402]  169.47 14.38 90 top
RD55  -  [R_0402]  119.26 12.56 180 top
RD56  -  [R_0402]  167.12 12.78 90 top
RD57  -  [R_0402]  123.56 22.32 90 top
RD58  -  [R_0402]  167.63 20.56 270 top
RD59  -  [R_0402]  123.03 19.92 180 top
RD60  -  [R_0402]  170.89 17.06 180 top
RD61  -  [R_0402]  125.39 17.18 0 top
RD62  -  [R_0402]  169.74 19.34 180 top
RD63  -  [R_0402]  123.03 19.03 180 top
RD64  -  [R_0402]  169.74 20.23 180 top
RD65  -  [R_0402]  123.03 20.8 180 top
RD66  -  [R_0402]  172.51 16.3 0 top
RD67  -  [R_0402]  121.78 17.24 90 top
RD68  -  [R_0402]  168.2 16.67 90 top
RD69  -  [R_0402]  118.86 16.37 270 top
RD70  -  [R_0402]  172.53 15.43 270 top
RD71  -  [R_0402]  122.7 17.21 90 top
RD72  -  [R_0402]  171.69 20.54 90 top
RD73  -  [R_0402]  108.91 19.6 180 top
RD74  -  [R_0402]  194.49 19.87 270 top
RD75  -  [R_0402]  122.49 25.19 180 top
RD76  -  [R_0402]  169.81 24.42 180 top
RD77  -  [R_0402]  122.49 24.3 180 top
RD78  -  [R_0402]  169.81 23.53 180 top
RD79  -  [R_0402]  99.76 18.71 180 top
RD80  -  [R_0402]  108.96 21.81 90 top
RD81  -  [R_0402]  128.82 19.22 0 top
RD82  -  [R_0402]  135.5 20.44 270 top
RD83  -  [R_0402]  146.37 19.22 180 top
RD84  -  [R_0402]  157.98 20.44 270 top
RD85  -  [R_0402]  175.94 19.22 0 top
RD86  -  [R_0402]  178.44 21.06 180 top
RD87  -  [R_0402]  122.67 22.32 90 top
RD88  -  [R_0402]  125.39 16.3 0 top
RD89  -  [R_0402]  168.93 22.32 0 top
RD90  -  [R_0402]  172.51 17.18 0 top
RH2  -  [R_0402]  172.68 47.07 0 bottom
RH11  -  [R_0402]  162.25 35.28 90 bottom
RH12  -  [R_0402]  178.8 48.62 0 top
RH21  -  [R_0402]  113.09 56.62 0 top
RH23  -  [R_0402]  164.61 33.51 180 bottom
RH24  -  [R_0402]  162.07 31.61 180 bottom
RH25  -  [R_0402]  165.47 33.51 0 bottom
RH29  -  [R_0402]  214.57 44.04 90 bottom
RH31  -  [R_0402]  160.34 33.37 90 bottom
RH34  -  [R_0402]  160.34 35.28 90 bottom
RH35  -  [R_0402]  167.53 52.69 180 bottom
RH37  -  [R_0402]  167.53 50.91 180 bottom
RH38  -  [R_0402]  118.43 48.8 90 bottom
RH39  -  [R_0402]  119.37 47.86 0 bottom
RH40  -  [R_0402]  119.37 48.75 0 bottom
RH42  -  [R_0402]  156.46 36.18 0 bottom
RH43  -  [R_0402]  155.01 66.02 0 bottom
RH51  -  [R0402_0OHM]  115.07 63.08 90 bottom
RH53  -  [R_0402]  119.37 45.19 0 bottom
RH54  -  [R_0402]  186.49 55.81 270 top
RH56  -  [R_0402]  185.6 55.81 270 top
RH70  -  [R_0402]  174.95 36.51 270 bottom
RH72  -  [R_0402]  173.93 36.51 270 bottom
RH76  -  [R_0402]  147.31 67.67 0 bottom
RH77  -  [R_0402]  147.31 66.78 0 bottom
RH78  -  [R_0402]  174.26 52.43 180 bottom
RH79  -  [R_0402]  165.08 49.73 0 top
RH80  -  [R_0402]  168.89 50.53 0 top
RH81  -  [R_0402]  168.89 49.64 0 top
RH82  -  [R_0402]  166.62 51.8 0 bottom
RH83  -  [R_0402]  168.89 48.75 0 top
RH91  -  [R_0402]  167.53 54.47 180 bottom
RH95  -  [R_0402]  176.28 53.42 180 top
RH98  -  [R_0402]  177.78 56.24 0 top
RH99  -  [R_0402]  180.47 56.24 180 top
RH100  -  [R_0402]  167.51 49.16 180 bottom
RH103  -  [R_0402]  167.53 56.62 180 bottom
RH105  -  [R_0402]  178.8 52.99 180 top
RH107  -  [R_0402]  168.4 53.63 90 bottom
RH111  -  [R_0402]  177.2 53.88 90 top
RH113  -  [R_0402]  148.57 64.42 90 top
RH117  -  [R_0402]  151.26 64.5 180 top
RH123  -  [R_0402]  174.73 66.2 90 top
RH126  -  [R_0402]  167.71 36.51 270 bottom
RH128  -  [R0402_0OHM]  169.88 47.58 270 top
RH131  -  [R_0402]  165.08 54.26 0 top
RH132  -  [R0402_0OHM]  166.95 51.11 270 top
RH133  -  [R0402_0OHM]  167.84 34.35 270 bottom
RH134  -  [R_0402]  166 53.4 180 top
RH137  -  [R0402_0OHM]  176.92 49.11 0 top
RH146  -  [R_0402]  173.64 47.25 180 top
RH147  -  [R_0402]  161.3 33.37 90 bottom
RH151  -  [R_0402]  161.3 35.28 90 bottom
RH154  -  [R_0402]  175.82 45.16 180 bottom
RH158  -  [R_0402]  163.01 66.99 270 bottom
RH159  -  [R_0402]  168.73 33.43 90 bottom
RH160  -  [R_0402]  166.62 45.45 0 bottom
RH163  -  [R_0402]  156.83 45.58 0 top
RH168  -  [R_0402]  182.95 49.04 90 top
RH171  -  [R_0402]  183.01 48.12 180 top
RH180  -  [R_0402]  171.38 54.14 90 top
RH183  -  [R_0402]  186.49 49.51 270 top
RH186  -  [R_0402]  169.04 47.35 180 top
RH196  -  [R_0402]  170.11 54.14 90 top
RH248  -  [R_0402]  169.22 55.05 270 top
RH256  -  [R_0402]  166.95 52.86 270 top
RH258  -  [R_0402]  184.66 55.23 180 top
RH270  -  [R_0402]  166.86 54.08 0 top
RH271  -  [R_0402]  170.69 52.1 270 top
RH272  -  [R_0402]  166.59 47.18 0 bottom
RH274  -  [R_0402]  172.41 50.45 90 bottom
RH281  -  [R_0402]  157.66 66.99 270 bottom
RH282  -  [R_0402]  159.44 66.99 270 bottom
RH293  -  [R0402_0OHM]  174.48 47.35 0 top
RH294  -  [R_0402]  170.17 34.65 0 bottom
RH295  -  [R_0402]  175.2 51.37 270 bottom
RH296  -  [R_0402]  181.03 47.62 90 top
RH297  -  [R0402_0OHM]  176.4 46.03 0 bottom
RH298  -  [R_0402]  179.71 47.61 180 top
RH299  -  [R_0402]  177.02 47.61 0 top
RH300  -  [R_0402]  161.23 66.99 270 bottom
RH301  -  [R_0402]  172.12 56.29 90 top
RH302  -  [R_0402]  166.59 50.05 0 bottom
RH303  -  [R_0402]  172.03 36.51 270 bottom
RH309  -  [R_0402]  171.09 33.64 180 bottom
RH310  -  [R_0402]  169.04 46.46 180 top
RH313  -  [R_0402]  166.69 35.59 90 bottom
RH314  -  [R_0402]  171.58 51.19 90 top
RH315  -  [R_0402]  171.58 53.2 180 top
RH316  -  [R_0402]  171.14 35.59 90 bottom
RH337  -  [R_0402]  173.35 51.29 0 bottom
RH338  -  [R_0402]  147.5 65.34 270 top
RH340  -  [R0805_0OHM]  154.28 49.6 180 top
RH341  -  [R0603_0OHM]  155.76 45.51 90 top
RH346  -  [R0402_0OHM]  153.17 47.35 180 top
RH348  -  [R_0603]  182.05 49.54 180 top
RH350  -  [R_0603]  186.94 68.87 0 top
RH351  -  [R_0603]  170.87 49.96 270 top
RH354  -  [R_0603]  184.88 67.56 0 bottom
RH355  -  [R0603_0OHM]  161.79 65.64 180 top
RH356  -  [R0603_0OHM]  160.97 67.1 90 top
RH360  -  [R_0402]  180.4 28.22 0 top
RH363  -  [R_0402]  117.91 56.12 180 top
RH364  -  [R_0402]  177.23 12.1 180 bottom
RH365  -  [R_0402]  178.1 12.1 0 bottom
RH367  -  [R_0402]  117.91 55.1 180 top
RH369  -  [R_0402]  89.45 56.45 90 top
RH370  -  [R_0402]  85.41 56.83 90 top
RH371  -  [R_0402]  90.91 58.28 90 top
RH372  -  [R_0402]  87.95 62.11 180 bottom
RH373  -  [R_0402]  120.29 43.42 180 bottom
RH374  -  [R_0402]  118.43 45.53 270 bottom
RH375  -  [R_0402]  118.51 47.86 180 bottom
RH380  -  [R_0402]  167.6 59.23 180 bottom
RH381  -  [R_0402]  167.53 55.74 180 bottom
RH383  -  [R_0402]  175.95 49.47 180 top
RH384  -  [R_0402]  174.17 56.29 90 top
RH386  -  [R_0402]  180.4 27.33 0 top
RH387  -  [R_0402]  162.12 66.99 270 bottom
RH388  -  [R_0402]  158.55 66.99 270 bottom
RH389  -  [R_0402]  156.79 66.99 270 bottom
RH390  -  [R_0402]  166.62 53.58 0 bottom
RH391  -  [R_0402]  173.67 55.1 270 bottom
RH392  -  [R_0402]  166.59 48.27 0 bottom
RH394  -  [R_0402]  162.25 34.29 270 bottom
RH396  -  [R_0402]  166.96 56.57 180 top
RH397  -  [R_0402]  166.96 57.44 180 top
RH400  -  [R_0402]  172.92 36.51 270 bottom
RH401  -  [R_0402]  168.6 36.51 270 bottom
RH402  -  [R_0402]  165.08 48.84 0 top
RH403  -  [R_0402]  170.25 35.59 90 bottom
RH405  -  [R_0603]  168.09 58.09 180 bottom
RH406  -  [R_0603]  178.19 57.77 0 bottom
RH410  -  [R_0402]  228.2 49.96 0 top
RH411  -  [R_0402]  120.29 44.31 180 bottom
RH412  -  [R_0402]  117.54 48.8 90 bottom
RH413  -  [R_0402]  90.34 56.45 90 top
RH414  -  [R_0402]  90.02 59.19 270 top
RH417  -  [R_0402]  175.86 51.44 90 top
RH418  -  [R_0402]  169.31 50.78 180 bottom
RH419  -  [R0402_0OHM]  35.59 24.01 0 top
RH420  -  [R_0402]  36.51 24.95 180 top
RH423  -  [R_0402]  201.56 36.05 180 top
RH424  -  [R_0402]  165.8 66.06 90 bottom
RH425  -  [R_0402]  164.92 66.06 90 bottom
RH427  -  [R0402_0OHM]  168.13 45.58 0 top
RH428  -  [R_0402]  180.4 29.13 0 top
RH429  -  [R_0402]  175.39 46.12 180 bottom
RH430  -  [R_0402]  176.38 46.92 0 bottom
RH431  -  [R_0402]  200.21 33.31 90 top
RH434  -  [R_0402]  165.13 56.5 90 top
RH436  -  [R_0402]  163.51 67.98 90 top
RH437  -  [R_0402]  162.62 67.98 90 top
RH438  -  [R_0402]  165.08 55.13 0 top
RH439  -  [R_0402]  174.48 46.46 0 top
RH440  -  [R_0402]  173.28 56.29 90 top
RH441  -  [R_0402]  175.37 54.34 0 top
RH442  -  [SHORTPADS]  172.66 53.96 270 top
RH443  -  [SHORTPADS]  174.06 54.34 270 top
RH444  -  [R_0402]  113.1 57.51 0 top
RH445  -  [R_0402]  119.37 46.85 0 bottom
RH446  -  [R_0402]  117.6 43.67 0 bottom
RH447  -  [R_0402]  199.32 64.55 90 top
RH448  -  [R0402_0OHM]  198.43 65.46 270 top
RH450  -  [R0402_0OHM]  166.93 48.42 90 top
RH451  -  [R_0402]  117.91 54.21 180 top
RH452  -  [R_0402]  167.77 54.97 180 top
RH453  -  [R_0402]  214.94 67.47 90 top
RH454  -  [R_0402]  211.58 66.66 270 top
RH455  -  [R_0402]  172 54.36 90 bottom
RH456  -  [R_0402]  171.16 55.35 180 bottom
RH457  -  [R_0402]  166.68 60.12 0 bottom
RH458  -  [R_0402]  166.67 65.06 0 bottom
RH459  -  [R_0402]  166.69 61.12 90 bottom
RH460  -  [R_0402]  166.67 64.17 0 bottom
RH461  -  [R_0402]  166.69 66.06 90 bottom
RH462  -  [R_0402]  164.03 66.06 90 bottom
RH463  -  [R_0402]  171.16 54.36 180 bottom
RH464  -  [R_0402]  167.06 45.32 90 top
RH465  -  [R_0402]  158.12 54.97 180 top
RH466  -  [R_0402]  165.11 45.83 0 top
RH467  -  [R_0402]  165.11 47.63 0 top
RH468  -  [R_0402]  165.11 46.72 0 top
RH469  -  [R_0402]  171.04 48.37 90 bottom
RH470  -  [R_0402]  170.15 48.37 90 bottom
RH471  -  [R_0402]  169.26 48.37 90 bottom
RH472  -  [R_0402]  168.37 48.37 90 bottom
RP3  -  [RP_0804_8P4R]  159.11 33.76 90 bottom
RP4  -  [RP_0804_8P4R]  179.21 50.25 180 top
RP5  -  [RP_0804_8P4R]  183.67 51.95 180 top
RP21  -  [RP_0804_8P4R]  213.54 57.83 0 bottom
RP22  -  [RP_0804_8P4R]  206.24 51.68 180 top
RR2  -  [R0402_0OHM]  268.79 16.06 270 top
RR3  -  [R0402_0OHM]  269.68 16.06 270 top
RR4  -  [R0402_0OHM]  270.55 16.06 270 top
RR5  -  [R0402_0OHM]  269.13 19.3 180 bottom
RR6  -  [R_0402]  265.5 18.86 270 bottom
RR7  -  [R0402_0OHM]  269.13 20.19 180 bottom
RR8  -  [R0402_0OHM]  269.13 21.06 180 bottom
RR9  -  [R_0402]  267.01 28.38 270 top
RR10  -  [R_0402]  266.25 24.54 90 top
RR11  -  [R0402_0OHM]  266.69 15.98 0 bottom
RR12  -  [R0402_0OHM]  270.31 24.54 90 top
RR13  -  [R0402_0OHM]  269.42 24.54 90 top
RR14  -  [R0402_0OHM]  269.13 21.95 180 bottom
RR15  -  [R0402_0OHM]  268.53 24.54 90 top
RR16  -  [R0402_0OHM]  267.65 24.54 90 top
RR18  -  [R0402_0OHM]  266.06 27.47 90 top
RTCD1  -  [BAT54CW-7-F_SOT323-3]  256.74 37.49 180 top
RTCR1  -  [R_0402]  261.42 43.11 270 top
RV16  -  [R_0402]  28.77 31.56 270 top
RV17  -  [R_0402]  28.81 33.51 0 top
RV18  -  [R_0402]  26.99 31.56 270 top
RV19  -  [R_0402]  30.66 34.73 270 top
RV20  -  [R_0402]  25.38 34.15 0 top
RV21  -  [R_0402]  27.88 31.56 270 top
RV22  -  [R_0402]  28.77 31.56 270 bottom
RV24  -  [R_0402]  26.99 31.56 270 bottom
RV26  -  [R_0402]  25.38 35.03 0 top
RV27  -  [R_0402]  27.88 31.56 270 bottom
RV28  -  [R_0402]  26.55 41.02 270 top
RV29  -  [R_0402]  27.44 41.02 270 top
RV30  -  [R_0402]  26.3 36.81 180 top
RV31  -  [R_0402]  26.1 30.64 90 bottom
RV32  -  [R_0402]  29.28 40.04 90 top
RV33  -  [R_0402]  28.39 40.04 90 top
SW2  -  [SW_T3AL-23-Q-T-R_4P]  276.97 4.03 180 bottom
T2  -  [TPC12]  122.62 56.37 180 bottom
T123  -  [TPC12]  165.5 49.04 180 bottom
T226  -  [TPC12]  121.35 59.04 180 bottom
T227  -  [TPC12]  122.69 59.04 180 bottom
T228  -  [TPC12]  123.03 52.76 180 bottom
T229  -  [TPC12]  121.55 60.31 180 bottom
T230  -  [TPC12]  121.35 52.43 180 bottom
T231  -  [TPC12]  122.75 57.64 180 bottom
T242  -  [TPC12]  204.83 23.5 0 top
T243  -  [TPC12]  204.45 25.13 0 top
T244  -  [TPC12]  203.13 25.76 90 bottom
T245  -  [TPC12]  203.1 27.08 180 bottom
T246  -  [TPC12]  203.31 28.43 180 bottom
T252  -  [TPC12]  250.39 65.2 0 top
T254  -  [TPC12]  22.51 20.15 0 top
T260  -  [TPC12]  247.63 59.1 0 top
T261  -  [TPC12]  248.98 59.09 0 top
T263  -  [TPC12]  121.35 57.77 180 bottom
T264  -  [TPC12]  121.35 56.45 180 bottom
T265  -  [TPC12]  122.4 57.87 90 top
T266  -  [TPC12]  126.56 59.99 0 top
T267  -  [TPC12]  120.67 57.11 180 top
T268  -  [TPC12]  125.16 62.85 0 top
T269  -  [TPC12]  122.88 64.37 0 top
T270  -  [TPC12]  165.55 52.94 180 bottom
T271  -  [TPC12]  165.55 54.28 180 bottom
T272  -  [TPC12]  172.61 56.17 180 bottom
T273  -  [TPC12]  118.08 46.72 180 bottom
T274  -  [TPC12]  165.5 50.33 0 bottom
T275  -  [TPC12]  121.15 47.33 180 bottom
T276  -  [TPC12]  121.38 48.75 180 bottom
T277  -  [TPC12]  121.35 43.72 180 bottom
T278  -  [TPC12]  121.71 50.02 180 bottom
T279  -  [TPC12]  165.55 55.55 180 bottom
T280  -  [TPC12]  153.13 51.04 0 top
T281  -  [TPC12]  162.25 56.88 0 top
T282  -  [TPC12]  165.55 51.67 180 bottom
T283  -  [TPC12]  43.63 11.77 0 top
T284  -  [TPC12]  166.44 43.29 180 bottom
T285  -  [TPC12]  165.59 47.77 180 bottom
T286  -  [TPC12]  167.28 39.78 180 bottom
T287  -  [TPC12]  169.41 52.94 0 top
T288  -  [TPC12]  176.6 50.43 0 top
T289  -  [TPC12]  233.6 35.85 0 top
U1  -  [RTS5227-GR_QFN32_4X4]  265.37 21.51 270 top
U2  -  [W25Q32FVSSIQ_SO8]  180.54 48.43 180 bottom
U4  -  [APA2605QAI-TRG_QFN20_4X4]  24.33 8.5 270 top
U5  -  [SN74AHC1G04DCKR_SOT23-5]  269.49 48.16 270 top
U23  -  [PI3C3125LEX_TSSOP14]  203.36 68.65 270 top
U34  -  [KB9012BF-A3_LFBGA_128P]  206.86 55.94 270 bottom
U48  -  [W25Q64FVSSIQ_SO8]  186.24 48.43 180 bottom
U635  -  [SN74LVC1G06DCKR_SC70-5]  105.55 36.34 180 bottom
U636  -  [STM32F103RDY6TR_WLCSP_64P]  246.34 60.34 90 top
U652  -  [AT97SC3204-X2A18-AB_TSSOP28]  213.07 39.81 180 bottom
U663  -  [74CBTLV3126BQ_DHVQFN14_2P5X3]  84.94 60.52 0 top
U664  -  [TPS22966DPUR_SON14_2X3]  33.37 15.94 0 bottom
U671  -  [TXB0104PWR_TSSOP14]  232.16 62.43 0 top
U672  -  [74AUP1G07GW_TSSOP5]  121.74 52.31 180 top
U673  -  [NCP4545IMNTWG_QFN18_3X3]  183.94 65.58 180 top
U675  -  [SN74AHC1G08DCKR_SC70-5]  218.12 51.34 270 top
U676  -  [SN74CBT1G125DCKR_SC70-5]  218.25 46.26 270 top
U677  -  [TXB0104PWR_TSSOP14]  226.2 62.43 0 top
U678  -  [SN74AHC1G08DCKR_SC70-5]  265.76 23.98 180 bottom
U679  -  [TXB0102YZPR_DSBGA_8P]  219.76 53.59 180 top
U682  -  [SN74AHC1G04DCKR_SOT23-5]  202.64 34.6 180 top
U690  -  [SN74AHC1G08DCKR_SC70-5]  182.07 33.65 270 top
U691  -  [SN74AHC1G08DCKR_SC70-5]  182.46 31.11 270 top
U697  -  [SN74AHC1G08DCKR_SC70-5]  87.31 64.1 90 top
U698  -  [SN74AHC1G08DCKR_SC70-5]  203.89 43.43 270 top
U699  -  [SN74AHC1G32DCKR_SC70-5]  262.3 45.16 0 top
U700  -  [SN74AHC1G32DCKR_SC70-5]  29.18 54.61 270 bottom
U708  -  [SN74AHC1G04DCKR_SOT23-5]  95.06 62.87 90 top
U709  -  [SN74AHC1G04DCKR_SOT23-5]  219.98 47.44 90 top
U710  -  [SN74AHC1G04DCKR_SOT23-5]  199.32 54.47 180 top
U712  -  [SN74AHC1G04DCKR_SOT23-5]  200.84 55.1 0 bottom
U713  -  [SN74AHC1G04DCKR_SOT23-5]  181.72 68.7 270 top
U714  -  [1337GNLGI8_QFN16_3X3]  245.3 45.8 0 top
U715  -  [TPS22966DPUR_SON14_2X3]  190.23 51.27 270 top
U716  -  [TPS22966DPUR_SON14_2X3]  241.43 53.04 270 top
U717  -  [TPS22966DPUR_SON14_2X3]  51.73 12.42 270 top
U718  -  [TPS22966DPUR_SON14_2X3]  234.87 49.12 270 top
U719  -  [TPS22966DPUR_SON14_2X3]  171.39 66.53 90 top
U720  -  [TPS22965DSGR_SON8_2X2]  266.01 8.34 0 top
U721  -  [TPS22965DSGR_SON8_2X2]  195.92 48.84 0 top
U722  -  [PS8401ATQFN40GTR-A3_TQFN40_5X5]  30.68 37.61 270 bottom
U724  -  [TPS22965DSGR_SON8_2X2]  202.36 10.35 180 top
U725  -  [AH1806-W-7_SC59-3]  288.1 37.84 270 top
UA1  -  [ALC5505_QFN48_7X7]  42.14 8.34 90 top
UA2  -  [ALC3661-CG_MQFN48_6X6]  29.32 22.1 90 top
UA3  -  [MAX9892ERTLFT_UCSP_6P]  18.09 19.22 180 top
UC1  -  [74AUP1G07GW_TSSOP5]  123.88 35.93 0 bottom
UCPU1  -  [SHARK-BAY-ULT_BGA_1168P-T]  163.46 62.81 0 bottom
UD1  -  [MT41J256M16RE-15E-D_FBGA_96P]  107.46 27.12 180 bottom
UD2  -  [MT41J256M16RE-15E-D_FBGA_96P]  119.01 27.12 180 bottom
UD4  -  [MT41J256M16RE-15E-D_FBGA_96P]  132.09 27.12 180 bottom
UD5  -  [MT41J256M16RE-15E-D_FBGA_96P]  143.65 27.12 180 bottom
UD6  -  [MT41J256M16RE-15E-D_FBGA_96P]  154.7 27.12 180 bottom
UD7  -  [MT41J256M16RE-15E-D_FBGA_96P]  166.26 27.12 180 bottom
UD9  -  [MT41J256M16RE-15E-D_FBGA_96P]  179.34 27.12 180 bottom
UD10  -  [MT41J256M16RE-15E-D_FBGA_96P]  190.9 27.12 180 bottom
UH5  -  [SN74AHC1G08DCKR_SC70-5]  185.38 49.63 180 top
US1  -  [TPS2543RTER_QFN16_3X3]  264.01 51.28 270 top
US2  -  [TPS2543RTER_QFN16_3X3]  28.73 46.28 90 top
Y1  -  [Y_CM31532768DZFT_2P]  242.45 60.75 90 top
Y2  -  [Y_7A08000006_2P]  249.58 68.39 180 top
Y3  -  [Y_Q13FC1350000200_2P]  241.23 48.66 270 top
YA1  -  [Y_X3G024000DC1H_4P]  45.43 10.16 270 top
YH1  -  [Y_CM31532768DZFT_2P]  172.26 48.7 0 bottom
YH2  -  [Y_X3G024000DC1H_4P]  151.81 68.31 180 top

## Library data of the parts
BRK1 = NCQF0_MB_SUP_BRK
C8 C9 C21 C44 C45 C48 C96 C265 C276-C283 C285 C286 C352 C355 C407 C612 C613 C617 C655 C656 C713-C715 C718 C720-C722 C963 C976-C979 C1061 C1063 C1102 C1110 C1116-C1118 C1123-C1125 C1134-C1140 C1145 C1152 C1158 C1160 C1161 C1163 C1164 C1173 C1199 C1200 C1202-C1205 C1212-C1216 C1219 C1225 C1227 C1228 C1230 C1237 C1241-C1248 C1251-C1254 C1256 C1257 C1261 C1262 C1278 C1280-C1290 C1292 C1294-C1304 CA4-CA6 CA10-CA18 CA24 CA26-CA35 CA37 CA38 CA40 CA41 CA47-CA50 CA53-CA56 CA58 CA68-CA71 CA74 CC233 CC234 CC238-CC240 CD1-CD5 CD14-CD19 CD24-CD28 CD37-CD42 CD45-CD49 CD58-CD63 CD68-CD72 CD81-CD86 CD89-CD98 CD102-CD107 CD111 CD112 CD115 CD116 CD119 CD120 CD123 CD124 CH1-CH7 CH11 CH16 CH23 CH24 CH39-CH41 CH47 CH82-CH85 CH95 CH1202 CH1203 CH1205-CH1207 CH1213-CH1216 CH1218 CH1222 CH1224 CH1226 CH1227 CH1229 CH1231-CH1236 CH1241 CR2 CR3 CR5 CR8 CR9 CR11 CR20 CV31 CV32 CV39 CV42-CV44 CV768 CV795 CV796 MC94-MC96 MC102-MC105 MC118 MC284 MC654 MC1133 MC1141 MC1151 MC1210-MC1212 MC1267-MC1277 PC101-PC108 PC112 PC113 PC116 PC202 PC203 PC208-PC212 PC216 PC220 PC227-PC229 PC343 PC345 PC429 PC433 PC437 PC440 PC501 PC502 PC509 PC511 PC512 PC603 PC604 PC609 PC614-PC616 PC708-PC711 PC714 PC718 PC721 PC724-PC726 = C_0402
C27 C29 C32 C42 C43 C46 C47 C50 C51 C293 C712 C716 C717 C719 C725 C962 C1059 C1143 C1153 C1159 C1162 C1172 C1209 C1231 C1240 CA1-CA3 CA7-CA9 CA19-CA23 CA25 CA36 CA39 CA42-CA46 CA51 CA57 CA67 CC160-CC165 CD20 CD21 CD43 CD44 CD64 CD65 CD87 CD88 CD101 CD110 CD113 CD114 CD117 CD118 CD121 CD122 CD125 CD126 CH1204 CH1217 CH1220 CH1223 CH1225 CH1239 CR1 CR4 CR6 CR7 CR10 CR12 CR19 CV40 CV41 PC114 PC115 PC213 PC218 PC221 PC318 PC329 PC333 PC335 PC342 PC347 PC427 PC439 PC503 PC504 PC605 PC608 PC612 PC613 PC707 PC712 PC713 PC715 PC717 PC720 = C_0603
C303 C1109 CH1230 = C_1206
C621 C623 C1060 C1062 C1064-C1069 C1107 C1108 CH25 CH26 CH1237 CH1238 CH1242 CH1243 CR13 CR14 CS42 CS43 CS53 CS54 CV8 CV10 CV27-CV30 CV33-CV38 CV45-CV50 = C_0402: signal model: C_0402NEW
CA52 CH1212 CH1228 CH1240 = C_A1
CD22 CD66 PC326 PC334 PC611 PC705 = C_B2
CH1208-CH1211 PC204 PC205 PC214 PC217 PC219 PC223-PC225 PC324 PC328 PC426 PC428 PC430 PC432 PC434 PC436 PC441 PC505-PC508 PC510 PC513 PC602 PC606 PC607 PC701-PC704 PC801-PC830 = C_0805
CLRP1 CLRP2 RH442 RH443 = SHORTPADS: User Part Number: PART#
D3 D4 D111 = RB751V-40GTE-17_SOD323-2
D72 D83 D104-D106 D115 D306 D307 = BAT54CW_SOT323-3
D81 D86 D87 D114 D305 = SDMK0340L-7-F_SOD323-2
D93 D301-D303 = DB2J31400L_SOD323-2
D110 = BAT1000-7-F_SOT23-3
DA1 DA2 DA5 DA6 DA8 DA9 = PJDLC05_SOT23-3
DA3 DA4 = PJDLC05C_SOT23-3
DE1 DE2 = PESD5V0U2BT_SOT23-3
DH5 PD201 = RB751V-40_SOD323-2
DV4 DV5 = AZ1045-04F_DFN2510P10E-10-9
F1 = F_1812L075-24DR
FD1-FD6 = FIDUCIAL_C40M80
FV2 = F_SMD1812P110TF
H1 H2 H6 H7 H18 = H_2P4
H4 = H_3P0
H9-H12 = H_3P9
H15 H26 = H_3P3
H19 = H_1P6N
H20 = H_2P4X1P6N
JAPS = E-T_6705K-Y18N-00L_18P
JBATT1 = FOX_GS73091-10272-7H_9P-T
JBL1 JROT1 JVOL = ACES_51522-00401-001_4P-T
JCARD = T-SOL_156-2001302603_19P-T
JDCIN1 = ACES_50281-00501-001_5P-T
JDEBUG = ACES_50281-0120N-001_12P
JFAN1 = HB_A510810-SCHR21_8P
JHDMI = ACON_HMR2G-AK120C_19P-T
JHP1 = SINGA_2SJ3061-030111F_6P-T
JKB1 = ACES_51522-01001-001_10P
JKB2 JSNRDG = ACES_50696-02001-001_20P-T
JLVDS1 = ACES_50406-02071-001_20P
JLVDS2 = STARC_300E50-0011RA-G3_50P
JNFC1 = HB_A531515-SCHR21_15P-T
JNGFF1 = LOTES_APCI0019-P001A01_67P-T
JNGFF2 = JAE_SM3ZS067U215ALL_75P-T
JP1 PJP304 PJP306 PJP501 PJP602 = JUMP_43X118
JPA1-JPA3 PJP409-PJP412 PJP603 PJP604 = JUMP_43X39
JPWR1 = HB_A520620-SCHR22_6P
JSATA1 = LCN_DAN08-52216-0100_52P
JSPK1 = CVILU_CI4304M2HR0-NH_4P
JTP1 = ACES_51522-01201-001_12P
JUSB1 JUSB2 = TAIWI_USB022-107CRL-TW_10P-T
JXDP = SAMTE_BSH-030-01-L-D-A_60P
L1 = MURAT_BLM21PG600SN1D_2P
L2-L5 = MURAT_BLM18PG181SN1D_L0603_2P
L43 L44 = KC_FBMA-L11-160808-800LMT_2P
L61-L63 LH10-LH12 = MURAT_LQM2MPN2R2NG0L_2P
L64-L67 = MURAT_DLW21SN900HQ2L_0805_4P
LA1 = CYNTE_PG031B-4R7MS_2P
LED2 = LED_LTW-C193TS5_2P
LH2 = MURAT_BLM18BA220SN1D_2P
MD50 MD90 = IP4223CZ6_SO6
MD74 MD82 = AZ1065-06QPRDG_MSOP8
ML40 ML52 ML55 = MURAT_DLW21HN900SQ2L_4P: signal model: SW_WCM2012F2S_4P
ML45 ML46 ML53 ML54 ML56-ML60 = MURAT_DLW21SN670HQ2L_4P
ML49 ML50 = SW_WCM2012F2S_4P
MR226 MR976 R741-R744 R1004-R1015 R1373 R1374 RA36 RA52-RA54 RH360 RH386 RH428 = R_0402: signal model: R_0402NEW
MR256 MR257 PH701 PH702 PR102-PR106 PR108-PR113 PR116 PR118-PR121 PR123-PR126 PR203 PR206 PR208 PR213 PR223-PR226 PR230 PR311 PR316 PR318 PR348 PR351-PR354 PR422 PR425 PR427 PR433 PR437 PR438 PR604 PR608 PR610 PR611 PR701-PR704 PR706-PR714 PR717 PR720 PR721 PR723 PR726 PR727 PR735-PR737 PR744 PR745 R1 R4 R7 R11 R23-R27 R31 R34 R36 R162 R163 R219 R221 R225 R229 R230 R232 R233 R240 R290 R296-R298 R300 R341 R342 R501 R503 R535-R537 R540 R545 R604 R607 R608 R746 R854 R855 R884 R886 R922 R923 R930 R931 R933 R935-R940 R942-R951 R953 R955 R957 R973 R975-R979 R985 R986 R989 R1003 R1026 R1033-R1036 R1090 R1092 R1099 R1100 R1103 R1116-R1120 R1132 R1136 R1137 R1140-R1143 R1152 R1153 R1156 R1157 R1161 R1162 R1164 R1165 R1168-R1170 R1174 R1179 R1180 R1182 R1185-R1187 R1190 R1197 R1198 R1200 R1202 R1203 R1205 R1208 R1210-R1217 R1220 R1223-R1225 R1228-R1230 R1233-R1237 R1239 R1241 R1243 R1249-R1251 R1253 R1255 R1256 R1261-R1266 R1289-R1292 R1295 R1296 R1300 R1301 R1310-R1313 R1324 R1325 R1327 R1328 R1338-R1343 R1346-R1351 R1360-R1371 R1376 R1381-R1386 R1390 RA1 RA5-RA8 RA14-RA18 RA20-RA25 RA27-RA31 RA33 RA35 RA37-RA39 RA41-RA45 RA48-RA51 RA55 RA56 RA58-RA62 RA75 RC36 RC41 RC43-RC46 RC48 RC52 RC54 RC55 RC58 RC60 RC75 RC81 RC93 RC95 RC97 RC100 RC138 RC146 RC149 RC153-RC156 RC158-RC161 RD1 RD2 RD5-RD8 RD11-RD90 RH2 RH11 RH12 RH21 RH23-RH25 RH29 RH31 RH34 RH35 RH37-RH40 RH42 RH43 RH53 RH54 RH56 RH70 RH72 RH76-RH83 RH91 RH95 RH98-RH100 RH103 RH105 RH107 RH111 RH113 RH117 RH123 RH126 RH131 RH134 RH146 RH147 RH151 RH154 RH158-RH160 RH163 RH168 RH171 RH180 RH183 RH186 RH196 RH248 RH256 RH258 RH270-RH272 RH274 RH281 RH282 RH294-RH296 RH298-RH303 RH309 RH310 RH313-RH316 RH337 RH338 RH363-RH365 RH367 RH369-RH375 RH380 RH381 RH383 RH384 RH387-RH392 RH394 RH396 RH397 RH400-RH403 RH410-RH414 RH417 RH418 RH420 RH423-RH425 RH429-RH431 RH434 RH436-RH441 RH444-RH447 RH451-RH472 RR6 RR9 RR10 RTCR1 RV16-RV22 RV24 RV26-RV33 = R_0402
PBJ1 = BJ_CR2016-L01-JHLF_2P
PC610 = C_B
PD103 PD104 = PESD24VS2UT_SOT23-3
PD202 = BAT54HT1G_SOD323-2
PD204 = SX34H_SMA2
PJP601 = JUMP_43X79
PL101 PL104-PL106 PL201 PL202 PL501 PL601 = TAI-T_HCB2012KF-121T50_2P
PL102 = MURAT_BLM15AG102SN1D_2P
PL203 PL602 = CYNTE_PCMB063T-2R2MS_2P
PL302 = TOKO_FDSD0630-H-3R3M-P3_2P
PL303 = TOKO_FDSD0630-H-2R2M-P3_2P
PL304 = KC_FBMA-L11-201209-121LMA50_2P
PL405 PL406 = TAIYO_NRS4018T1R0NDGJ_2P
PL502 = CYNTE_PCMC063T-R68MN_2P
PL701 = MAG_MMD06CZER15MG_4P
PL703 = KC_FBMA-L11-453215800LMA90T_2P
PQ101 = FDV301N-G_SOT23-3
PQ102 = MMST3904-7-F_SOT323-3
PQ103 = 2N7002KDWH_SOT363-6
PQ104 PQ106 PQ202 PQ204 = 2N7002KW_SOT323-3
PQ105 Q352 Q359 Q366 Q367 QA1 QA3 QA6 QH3 QH4 = DMN66D0LDW-7_SOT363-6
PQ201 = CSD87312Q3E_SON8-4
PQ203 = SIR472DP-T1-GE3_POWERPAK8-5
PQ205 = SI7716ADN-T1-GE3_POWERPAK8-5
PQ206 = AO4407AL_SO8
PQ304 PQ305 = CSD87330Q3D_SON8-7
PQ601 = MDV1528URH_PDFN33-8-5
PQ602 = MDV1524URH_PDFN33-8-5
PR115 PR238-PR240 PR335 PR344 PR345 PR404 PR405 PR428 PR434 PR505 PR508 PR613 PR615 PR718 R253 R265 R819 R921 R924 R934 R974 R982-R984 R987 R988 R990 R1016 R1017 R1131 R1133 R1135 R1158 R1166 R1167 R1188 R1204 R1209 R1218 R1219 R1227 R1231 R1232 R1238 R1252 R1257 R1258 R1294 R1297 R1309 R1314 R1353 R1387 R1388 RA3 RA4 RA9-RA13 RA26 RA57 RC49 RC98 RC99 RC147 RC148 RC150-RC152 RC162 RH51 RH128 RH132 RH133 RH137 RH293 RH297 RH346 RH419 RH427 RH448 RH450 RR11 RR14 RR18 = R0402_0OHM
PR122 PR209 PR210 PR220 PR312 PR313 PR429 PR432 PR507 PR605 PR719 R1240 R1355 = R_1206
PR201 PR216 = R_1206_4P-D
PR202 PR211 PR355 PR356 PR506 PR601 PR606 PR715 PR725 PR731 R531 R1129 R1305 R1306 R1321 R1326 R1379 RA46 RA47 RA68 RA69 RH348 RH350 RH351 RH354 RH405 RH406 = R_0603
PU201 = BQ24715RGRR_QFN20_3P5X3P5
PU301 = TPS51285BRUKR_QFN20_3X3
PU405 PU406 = TLV62150RGTR_QFN16_3X3
PU501 = TPS51362RVER_QFN28_4P5X3P5
PU601 = G5616ARZ1U_TQFN20_3X3
PU701 = TPS51622RSM_QFN32_4X4
PU702 = CSD97374CQ4M_SON8_3P5X4P5
Q4-Q6 Q34 Q39 Q71 Q107 Q134-Q136 Q305 Q311 Q326 Q344 Q346 Q348 Q350 Q351 Q362-Q365 QC5 = SSM3K7002FU_SC70-3
Q70 = SI3457BDV-T1-E3_TSOP6
Q329 Q330 = AO3419L_SOT23-3
